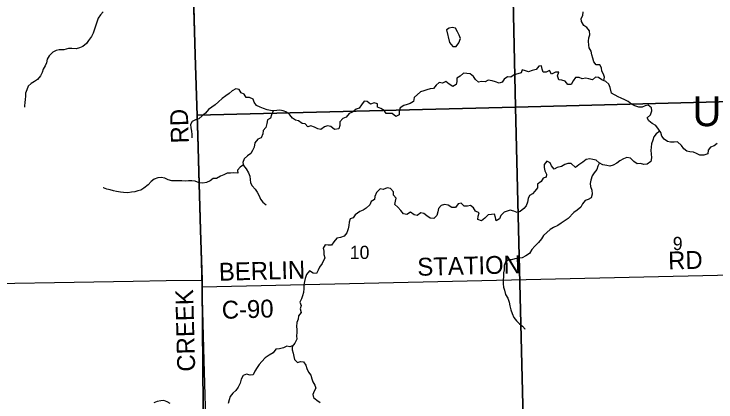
# Model space of a CAD drawing. Extents: x 0 to 34, y 0 to 22.
# Drawn here: x 6.498 to 8.73, y 14.793 to 16.025 of the extents above; entities that cross this region are included whole.
import ezdxf

# ---------------------------------------------------------------- set-up
doc = ezdxf.new("R2010")
doc.units = 0
for name, color, linetype in [('GM_X_Corporation', 7, 'Continuous'), ('GM_X_County_Road', 7, 'Continuous'), ('GM_X_County_Road_Text', 7, 'Continuous'), ('GM_X_Minor_Lake', 7, 'Continuous'), ('GM_X_Minor_Lake_Text', 7, 'Continuous'), ('GM_X_Minor_River', 7, 'Continuous'), ('GM_X_Section_Text', 7, 'Continuous'), ('GM_X_Township_Road', 7, 'Continuous')]:
    doc.layers.add(name, color=color, linetype=linetype)

msp = doc.modelspace()

# ---------------------------------------------------------------- linework, layer by layer
at = {"layer": 'GM_X_Corporation'}
for points in [[(7.068, 16.109), (7.0714, 16.0063), (7.0745, 15.896), (7.0787, 15.766), (7.0827, 15.6404), (7.0859, 15.5239), (7.0914, 15.3396), (7.0961, 15.1801), (7.0965, 15.1593), (7.1012, 14.6522), (7.1045, 14.5502), (7.1291, 13.6578), (8.1719, 13.6806), (8.628, 13.6922), (9.6344, 13.7177), (9.7208, 13.7198), (10.2438, 13.7323), (10.2438, 18.8341)], [(5.8662, 13.6357), (7.1049, 13.6572), (7.1291, 13.6578), (7.1045, 14.5502), (7.1012, 14.6522), (7.0965, 15.1593), (7.0961, 15.1801), (7.0914, 15.3396), (7.0859, 15.5239), (7.0827, 15.6404), (7.0787, 15.766), (7.0745, 15.896), (7.0714, 16.0063), (7.068, 16.109)]]:
    msp.add_lwpolyline(points, dxfattribs=at)
for points in [[(9.0769, 16.778), (9.1033, 15.7563), (8.0922, 15.7295), (8.0702, 16.7576)], [(8.0702, 16.7576), (8.0922, 15.7295), (7.0809, 15.7039), (7.0674, 16.1623), (7.0559, 16.7358)], [(9.1033, 15.7563), (9.132, 14.7248), (8.1182, 14.6962), (8.0922, 15.7295)], [(8.0922, 15.7295), (8.1182, 14.6962), (7.1099, 14.6684), (7.1027, 14.9246), (7.0857, 15.5512), (7.0809, 15.7039)]]:
    msp.add_lwpolyline(points, close=True, dxfattribs=at)
at = {"layer": 'GM_X_County_Road'}
for points in [[(7.1014, 14.6516), (7.0967, 15.1587), (7.0963, 15.1796), (7.0916, 15.3391), (7.0861, 15.5233), (7.0829, 15.6399), (7.0789, 15.7655), (7.0747, 15.8954), (7.0716, 16.0057), (7.0682, 16.1085), (7.0669, 16.1647), (7.0384, 17.644)], [(7.0967, 15.1587), (8.735, 15.1956), (8.8937, 15.199), (9.1804, 15.2086), (9.2686, 15.2111), (9.3914, 15.2147), (9.5125, 15.2213), (9.6156, 15.2242)]]:
    msp.add_lwpolyline(points, dxfattribs=at)
at = {"layer": 'GM_X_Minor_Lake'}
for points in [[(7.8831, 15.9346), (7.8939, 15.9225), (7.9041, 15.9226), (7.912, 15.934), (7.9176, 15.9478), (7.9137, 15.958), (7.9083, 15.9694), (7.9017, 15.9803), (7.8918, 15.9825), (7.8815, 15.9809), (7.8732, 15.9752)], [(7.8732, 15.9752), (7.8831, 15.9346)]]:
    msp.add_lwpolyline(points, dxfattribs=at)
at = {"layer": 'GM_X_Minor_River'}
for points in [[(6.7819, 16.033), (6.7733, 16.0226), (6.7654, 16.0127), (6.7617, 16.0001), (6.7576, 15.9868), (6.7539, 15.9772), (6.7502, 15.9651), (6.745, 15.9536), (6.7352, 15.9417)], [(8.3731, 15.8142), (8.3751, 15.8244), (8.372, 15.8343), (8.3673, 15.8442), (8.3657, 15.8544), (8.3607, 15.8646), (8.3496, 15.8638), (8.3416, 15.8736), (8.3388, 15.885), (8.3353, 15.896), (8.3333, 15.9074), (8.3267, 15.9176), (8.3263, 15.9271), (8.3246, 15.9396), (8.3253, 15.9499), (8.329, 15.9594), (8.3278, 15.9723), (8.3189, 15.9825), (8.3094, 15.9893), (8.302, 16.0018), (8.3019, 16.0116), (8.3068, 16.0212), (8.3075, 16.0322)], [(6.7352, 15.9417), (6.7288, 15.9314), (6.7171, 15.9226), (6.7065, 15.918), (6.6962, 15.9152), (6.6821, 15.9159), (6.6719, 15.9158), (6.6563, 15.9118), (6.6419, 15.9121), (6.632, 15.9101), (6.6218, 15.9047), (6.6105, 15.8932), (6.6037, 15.8822), (6.6012, 15.8707), (6.5974, 15.8604), (6.5914, 15.8505), (6.5873, 15.8402), (6.5829, 15.8288), (6.5727, 15.8177), (6.5629, 15.8115), (6.553, 15.805), (6.5432, 15.7958), (6.5395, 15.7847), (6.5351, 15.774), (6.5348, 15.7641), (6.5337, 15.7539), (6.5327, 15.7444), (6.532, 15.7333), (6.532, 15.7292)], [(8.691, 15.577), (8.6785, 15.5775), (8.6685, 15.5824), (8.6582, 15.5865), (8.6468, 15.5871), (8.6373, 15.5893), (8.6273, 15.5969), (8.6204, 15.6082), (8.6077, 15.6191), (8.5975, 15.6187), (8.5857, 15.6186), (8.5758, 15.6208), (8.5658, 15.6275), (8.5574, 15.6377), (8.5546, 15.6491), (8.5477, 15.6597), (8.5392, 15.6718), (8.527, 15.6774), (8.5166, 15.6857), (8.5116, 15.6955), (8.5214, 15.7055), (8.5262, 15.7181), (8.5246, 15.7279), (8.5147, 15.7355), (8.5048, 15.7343), (8.495, 15.73), (8.4843, 15.7291), (8.4721, 15.7336), (8.4614, 15.7392), (8.4511, 15.7471), (8.4404, 15.7531), (8.4289, 15.7584), (8.419, 15.7625), (8.3983, 15.7745), (8.3932, 15.7919), (8.3897, 15.8025), (8.3801, 15.8112), (8.3672, 15.8168), (8.3568, 15.8239), (8.3473, 15.8246), (8.3371, 15.8169), (8.3257, 15.8191), (8.3158, 15.8217), (8.3048, 15.8193), (8.2948, 15.8238), (8.2838, 15.8241), (8.2763, 15.8134), (8.2695, 15.8019), (8.2593, 15.8019), (8.2508, 15.8117), (8.2401, 15.8158), (8.2302, 15.8161), (8.2263, 15.8286), (8.2308, 15.8404), (8.2194, 15.8403), (8.2069, 15.8341), (8.2007, 15.8462), (8.1901, 15.8405), (8.1802, 15.8404), (8.1778, 15.8506), (8.1758, 15.8609), (8.1663, 15.86), (8.1584, 15.8497), (8.1459, 15.8458), (8.1342, 15.8415), (8.1239, 15.8445), (8.1143, 15.8486), (8.1106, 15.8383), (8.1, 15.8356), (8.0879, 15.8328), (8.0773, 15.8247), (8.067, 15.8258), (8.0568, 15.8185), (8.05, 15.8089), (8.0405, 15.8062), (8.0295, 15.8103), (8.018, 15.8136), (8.0062, 15.8151), (7.996, 15.81), (7.985, 15.8107), (7.9755, 15.8091), (7.9659, 15.817), (7.9594, 15.8268), (7.9482, 15.8355), (7.9383, 15.8366), (7.9273, 15.8372), (7.9171, 15.8284), (7.9062, 15.8215), (7.9066, 15.8116), (7.9037, 15.8017), (7.8931, 15.7948), (7.882, 15.8027), (7.8713, 15.8109), (7.8603, 15.8055), (7.8504, 15.8081), (7.8402, 15.7993), (7.8315, 15.789), (7.8209, 15.7874), (7.811, 15.785), (7.8015, 15.7815), (7.7901, 15.7787)], [(7.7901, 15.7787), (7.7705, 15.7603), (7.768, 15.7474), (7.7581, 15.7412), (7.7479, 15.7385), (7.7373, 15.7346), (7.7263, 15.7277), (7.723, 15.7163), (7.7227, 15.7048), (7.7121, 15.6994), (7.7006, 15.7092), (7.6911, 15.7099), (7.6816, 15.7095), (7.675, 15.7193), (7.6643, 15.7249), (7.6544, 15.7294), (7.6536, 15.74), (7.6429, 15.7437), (7.6319, 15.7387), (7.6208, 15.7477), (7.6113, 15.7481), (7.6026, 15.7373), (7.5955, 15.7259), (7.586, 15.7235), (7.5743, 15.7135), (7.5641, 15.7093), (7.5539, 15.6982), (7.5437, 15.6935), (7.5346, 15.6828), (7.534, 15.671), (7.5314, 15.6608), (7.5177, 15.6587), (7.5051, 15.6681), (7.4952, 15.6703), (7.4857, 15.6672), (7.4736, 15.6584), (7.4637, 15.6602), (7.4534, 15.6655), (7.442, 15.6699), (7.4321, 15.6668), (7.424, 15.677), (7.4145, 15.6781), (7.4026, 15.686), (7.3931, 15.6885), (7.3832, 15.6945), (7.3751, 15.7051), (7.3655, 15.7138), (7.3537, 15.7182), (7.3438, 15.7201), (7.3335, 15.7185), (7.3229, 15.7176), (7.3134, 15.7187), (7.3031, 15.7209), (7.2912, 15.7254), (7.2809, 15.7291), (7.2695, 15.7347), (7.2618, 15.7453), (7.259, 15.7547), (7.2468, 15.76), (7.2362, 15.7603), (7.2296, 15.7709), (7.2201, 15.7746), (7.2146, 15.7856), (7.2036, 15.7878), (7.1919, 15.7812), (7.182, 15.7735), (7.1714, 15.7658), (7.1605, 15.7566), (7.1484, 15.7466), (7.1378, 15.7374), (7.1276, 15.7294), (7.1163, 15.7224), (7.1069, 15.711), (7.0963, 15.7018), (7.0861, 15.6922), (7.0751, 15.6894), (7.0645, 15.684), (7.0597, 15.6741), (7.0609, 15.6638), (7.0629, 15.6528), (7.0641, 15.643), (7.0635, 15.6331), (7.0631, 15.6323)], [(7.322, 15.7177), (7.3173, 15.7054), (7.3139, 15.6947), (7.3041, 15.6897), (7.3023, 15.6776), (7.299, 15.665), (7.2903, 15.6554), (7.2889, 15.6451), (7.2844, 15.6326), (7.2731, 15.6279), (7.264, 15.616), (7.2619, 15.6027), (7.257, 15.592), (7.2507, 15.5825), (7.2408, 15.5748), (7.2295, 15.5652), (7.2262, 15.5538), (7.2278, 15.5443), (7.2363, 15.5333), (7.2436, 15.5212), (7.2475, 15.5099), (7.2495, 15.4992), (7.2503, 15.4894), (7.255, 15.4791), (7.2646, 15.469), (7.2708, 15.4591), (7.2777, 15.4478), (7.2816, 15.4375), (7.2897, 15.4277), (7.3, 15.4194)], [(8.5516, 15.6537), (8.5402, 15.6452), (8.5327, 15.6349), (8.5297, 15.625), (8.5249, 15.6135), (8.5238, 15.6025), (8.5232, 15.5922), (8.524, 15.5812), (8.5253, 15.5687), (8.5227, 15.5565), (8.511, 15.5481), (8.5011, 15.5472), (8.4901, 15.5502), (8.4798, 15.5497), (8.4691, 15.5568), (8.4584, 15.567), (8.4469, 15.5696), (8.4356, 15.5649), (8.4242, 15.5591), (8.4144, 15.5518), (8.403, 15.5449), (8.3924, 15.5422), (8.3825, 15.5444), (8.3703, 15.5462), (8.3588, 15.5529), (8.3492, 15.5616), (8.3386, 15.563), (8.3291, 15.5656), (8.3169, 15.5632), (8.3067, 15.5552), (8.2938, 15.5467), (8.2833, 15.5383), (8.2695, 15.5503), (8.2592, 15.5506), (8.2493, 15.5471), (8.2384, 15.5409), (8.2255, 15.5374), (8.2152, 15.532), (8.2068, 15.543), (8.2029, 15.5528), (8.1926, 15.5581), (8.1839, 15.5474), (8.1836, 15.5378), (8.1864, 15.5268), (8.191, 15.517), (8.19, 15.5067), (8.1805, 15.5036), (8.1741, 15.4929), (8.1624, 15.4845), (8.1625, 15.4727), (8.1539, 15.4631), (8.1467, 15.4536), (8.1369, 15.4489), (8.1328, 15.439), (8.131, 15.4272), (8.1269, 15.4165), (8.1186, 15.407), (8.1076, 15.3981), (8.0978, 15.3946), (8.0875, 15.3995), (8.0757, 15.4017), (8.0662, 15.3986), (8.0563, 15.3954), (8.0465, 15.3855), (8.0421, 15.3744), (8.0307, 15.3682), (8.0291, 15.3785), (8.026, 15.3891), (8.0161, 15.3887), (8.0054, 15.3878), (7.9949, 15.3767), (7.9843, 15.3679), (7.9732, 15.3727), (7.9739, 15.383), (7.9769, 15.3933), (7.9658, 15.3989), (7.9596, 15.4095), (7.9496, 15.4166), (7.9402, 15.415), (7.9295, 15.415), (7.9199, 15.4244), (7.9104, 15.422), (7.9014, 15.4109), (7.89, 15.4108), (7.8781, 15.418), (7.8671, 15.4202), (7.8568, 15.4174), (7.8478, 15.4078), (7.8456, 15.3964), (7.843, 15.3854), (7.8325, 15.3758), (7.8214, 15.3768), (7.8107, 15.3847), (7.8012, 15.3919), (7.7913, 15.3933), (7.7803, 15.3853), (7.7704, 15.3878), (7.7589, 15.3954), (7.7476, 15.3888), (7.7361, 15.3902), (7.7284, 15.4012)], [(8.734, 15.6136), (8.7239, 15.6067), (8.7122, 15.6019), (8.7055, 15.5924), (8.7045, 15.581), (8.6947, 15.5778), (8.691, 15.577)], [(7.2275, 15.5461), (7.2172, 15.5393), (7.2089, 15.5293), (7.2094, 15.5198), (7.1957, 15.5212), (7.1862, 15.5196), (7.1759, 15.5196), (7.1653, 15.5142), (7.1551, 15.5107), (7.1422, 15.5033), (7.1319, 15.5025), (7.1217, 15.4956), (7.11, 15.4905), (7.0982, 15.4885), (7.0864, 15.4892), (7.0738, 15.4944), (7.0639, 15.4955), (7.0533, 15.4958), (7.043, 15.4942), (7.032, 15.4952), (7.0217, 15.4959), (7.0103, 15.4951), (6.9996, 15.4953), (6.9886, 15.4983), (6.9775, 15.5039), (6.9665, 15.5057), (6.955, 15.5049), (6.9441, 15.501), (6.9339, 15.4937), (6.9244, 15.483), (6.9112, 15.4726), (6.901, 15.4657), (6.8915, 15.4633), (6.882, 15.4606), (6.8718, 15.459), (6.8604, 15.4577), (6.8467, 15.4588), (6.8372, 15.4591), (6.8242, 15.4613), (6.8147, 15.4638), (6.8036, 15.4668), (6.793, 15.4694), (6.7823, 15.4727), (6.7815, 15.4727)], [(8.3601, 15.5522), (8.354, 15.5422), (8.351, 15.5312), (8.3424, 15.5209), (8.3364, 15.5109), (8.3323, 15.4972), (8.3301, 15.4873), (8.3306, 15.4778), (8.3353, 15.4661), (8.3361, 15.4535), (8.3336, 15.4414), (8.3237, 15.4356), (8.3142, 15.4328), (8.3052, 15.4225), (8.3004, 15.4122), (8.2887, 15.4018), (8.2784, 15.3953), (8.2604, 15.3754), (8.2475, 15.3669), (8.2377, 15.3604), (8.2271, 15.3535), (8.2138, 15.3473), (8.2025, 15.3403), (8.1919, 15.3315), (8.1817, 15.3212), (8.175, 15.3116), (8.1656, 15.299), (8.1543, 15.2875), (8.1445, 15.2772), (8.137, 15.2646), (8.1252, 15.2576), (8.1139, 15.2511), (8.1021, 15.2495), (8.0907, 15.2471), (8.0797, 15.2447), (8.0702, 15.2443), (8.0604, 15.2373), (8.0571, 15.2259), (8.0564, 15.2126), (8.0546, 15.2031), (8.0543, 15.1905), (8.0529, 15.181), (8.0534, 15.1681), (8.055, 15.1579), (8.0581, 15.1476), (8.0613, 15.1347), (8.0679, 15.1222), (8.0729, 15.1094), (8.0745, 15.0987), (8.0773, 15.0858), (8.082, 15.0741), (8.0878, 15.0608), (8.0955, 15.0502), (8.1055, 15.0412), (8.115, 15.0337), (8.1231, 15.0235), (8.1235, 15.025)], [(7.7284, 15.4012), (7.7184, 15.4121), (7.7089, 15.42), (7.7111, 15.4303), (7.7133, 15.4402), (7.7048, 15.45), (7.7047, 15.4607), (7.6955, 15.4712), (7.6841, 15.4727), (7.6719, 15.4676), (7.662, 15.4698), (7.6503, 15.4587), (7.6459, 15.4458), (7.6441, 15.4359), (7.6335, 15.4301), (7.629, 15.419), (7.6181, 15.4083), (7.6082, 15.4021), (7.5976, 15.3982), (7.5833, 15.3879), (7.5769, 15.3779), (7.5666, 15.3744), (7.5641, 15.3645), (7.5626, 15.3539), (7.5604, 15.3432), (7.5568, 15.3303), (7.5481, 15.3199), (7.5364, 15.3149), (7.5242, 15.3137), (7.5148, 15.3014), (7.508, 15.2911), (7.4974, 15.291), (7.4875, 15.2917), (7.4815, 15.2818), (7.4831, 15.2715), (7.4836, 15.2609), (7.486, 15.2506), (7.4781, 15.2323), (7.4691, 15.2212), (7.465, 15.2113), (7.4598, 15.2006), (7.4491, 15.2025), (7.438, 15.2096), (7.4279, 15.1973), (7.4238, 15.1848), (7.422, 15.1752), (7.4198, 15.165), (7.4199, 15.1536), (7.4185, 15.1406), (7.4159, 15.1303), (7.4126, 15.1204), (7.4073, 15.1094), (7.4112, 15.0995), (7.4083, 15.0885), (7.4107, 15.0767), (7.4031, 15.066), (7.4021, 15.0557), (7.3972, 15.0451), (7.3962, 15.0329), (7.3978, 15.0234), (7.3971, 15.0139), (7.3961, 15.0032), (7.3973, 14.9918), (7.3914, 14.9796), (7.3827, 14.9689), (7.3824, 14.9587), (7.3863, 14.948), (7.3883, 14.9374), (7.3895, 14.9272), (7.3999, 14.9185), (7.4094, 14.9212), (7.4189, 14.9198), (7.4262, 14.9096), (7.4293, 14.8986), (7.4348, 14.8876), (7.4421, 14.8774), (7.4448, 14.866), (7.4483, 14.8562), (7.4545, 14.846), (7.458, 14.8361), (7.4528, 14.8266), (7.4483, 14.8166), (7.4503, 14.8072), (7.4606, 14.7989), (7.4714, 14.791)], [(7.3856, 14.9725), (7.3755, 14.9681), (7.3652, 14.9699), (7.3546, 14.9649), (7.3425, 14.9614), (7.331, 14.9605), (7.322, 14.9491), (7.3095, 14.9417), (7.2967, 14.9329), (7.2858, 14.9214), (7.2775, 14.9118), (7.2711, 14.9019), (7.2643, 14.8908), (7.2584, 14.8786), (7.2489, 14.8781), (7.2374, 14.8811), (7.2272, 14.8765), (7.2204, 14.8654), (7.2171, 14.8524), (7.2104, 14.8398), (7.2033, 14.8295), (7.1935, 14.8207), (7.1852, 14.8104), (7.1826, 14.7993), (7.1789, 14.7875)], [(6.9952, 14.7879), (6.9849, 14.7936), (6.9746, 14.7973), (6.9647, 14.7964), (6.9537, 14.7937), (6.9431, 14.7898)]]:
    msp.add_lwpolyline(points, dxfattribs=at)
at = {"layer": 'GM_X_Township_Road'}
msp.add_lwpolyline([(6.4372, 15.1693), (6.6899, 15.1737), (6.8766, 15.1768), (6.9817, 15.1787), (7.0963, 15.1796)], dxfattribs=at)

# ---------------------------------------------------------------- texts
at = {"layer": 'GM_X_County_Road_Text'}
for s, rotation, p in [('RD', 91.9757, (7.0544, 15.6154)), ('RD', 1.4806, (8.5786, 15.2135)), ('STATION', 1.4486, (7.7812, 15.1935)), ('BERLIN', 1.5223, (7.1503, 15.1777)), ('CREEK', 91.4688, (7.0744, 14.8898)), ('C-90', 1.714, (7.1597, 15.0567))]:
    msp.add_text(s, height=0.05682, rotation=rotation, dxfattribs=at).set_placement(p)
at = {"layer": 'GM_X_Minor_Lake_Text'}
msp.add_text('Upper Diehl', height=0.094732, rotation=359.9569, dxfattribs=at).set_placement((8.6554, 15.6691))
at = {"layer": 'GM_X_Section_Text'}
for s, height, p in [('9', 0.0419, (8.5926, 15.2754)), ('10', 0.04186, (7.5659, 15.2471))]:
    msp.add_text(s, height=height, rotation=0, dxfattribs=at).set_placement(p)

doc.saveas('drawing.dxf')
